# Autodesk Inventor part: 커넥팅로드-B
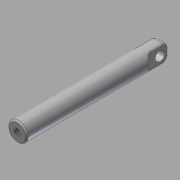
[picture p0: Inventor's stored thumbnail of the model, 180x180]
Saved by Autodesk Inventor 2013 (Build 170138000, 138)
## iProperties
Created: 2018-01
Part Number: 커넥팅로드-B
Material: 강철, 연강
Document SubType Name: Modeling
Designer: mduedu
Density: 7.86 g/cm^3
Mass: 14.5817 g
Surface Area: 12.9187 cm^2
Volume: 1.85518 cm^3
Author: mduedu
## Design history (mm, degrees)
sketch "스케치1"
  geometry: C1 r 3.5 at (0, 0); 1 further point
  constraints: 1 centre point, 1 coincident
  dimensions: "d0" = 7 diameter of C1
extrude "돌출1" new body sketch "스케치1" distance "d1" = 53; taper "d2" = 0 deg
node "작업 평면1"
sketch "스케치2"
  geometry: L1 (-3.5, 0)-(3.5, 0) reference; L2 (4, 4)-(4, 0); L3 (4, 0)-(-4, 0); L4 (-4, 0)-(-4, 4); A1 r 4 centre (0, 4) between (4, 4) and (-4, 4); 2 further points
  constraints: 6 end point, 2 perpendicular, 2 point on circle, 2 tangent, 1 centre point, 1 collinear, 1 midpoint, 1 vertical, 1 vertical alignment
  dimensions: "d4" = 8 diameter of A1; "d5" = 4 distance from line of A1.centre L1
extrude "돌출2" cut sketch "스케치2" stored distance "d6" = 53; taper "d7" = 0 deg
fillet "모깎기1" dims "d8" = 2
fillet "모깎기2" dims "d9" = 0.5
fillet "모깎기3" dims "d10" = 0.5
sketch "스케치3"
  geometry: C1 r 1.75 at (0, 3); 1 further point
  constraints: 1 centre point, 1 vertical alignment
  dimensions: "d11" = 3.5 diameter of C1; "d12" = 3 distance of point (0, 0) C1.centre
extrude "돌출3" cut sketch "스케치3" stored distance "d13" = 53; taper "d14" = 0 deg
chamfer "모따기1" distance "d15" = 0.5; stored, may be unused: second distance "d16" = 2, angle "d17" = 45 deg
sketch "스케치4"
  geometry: 1 further point
hole "구멍1" sketch "스케치4" at (0, 0) diameter "d18" = 2.459; stored, may be unused: countersink angle "d22" = 90 deg, drill point angle "d24" = 120 deg; dims "d19" = 6.9, "d20" = 4, "d21" = 2, "d23" = 8.4
node "솔리드1"
mirror "대칭1"
other parameters: "d3" = 2
